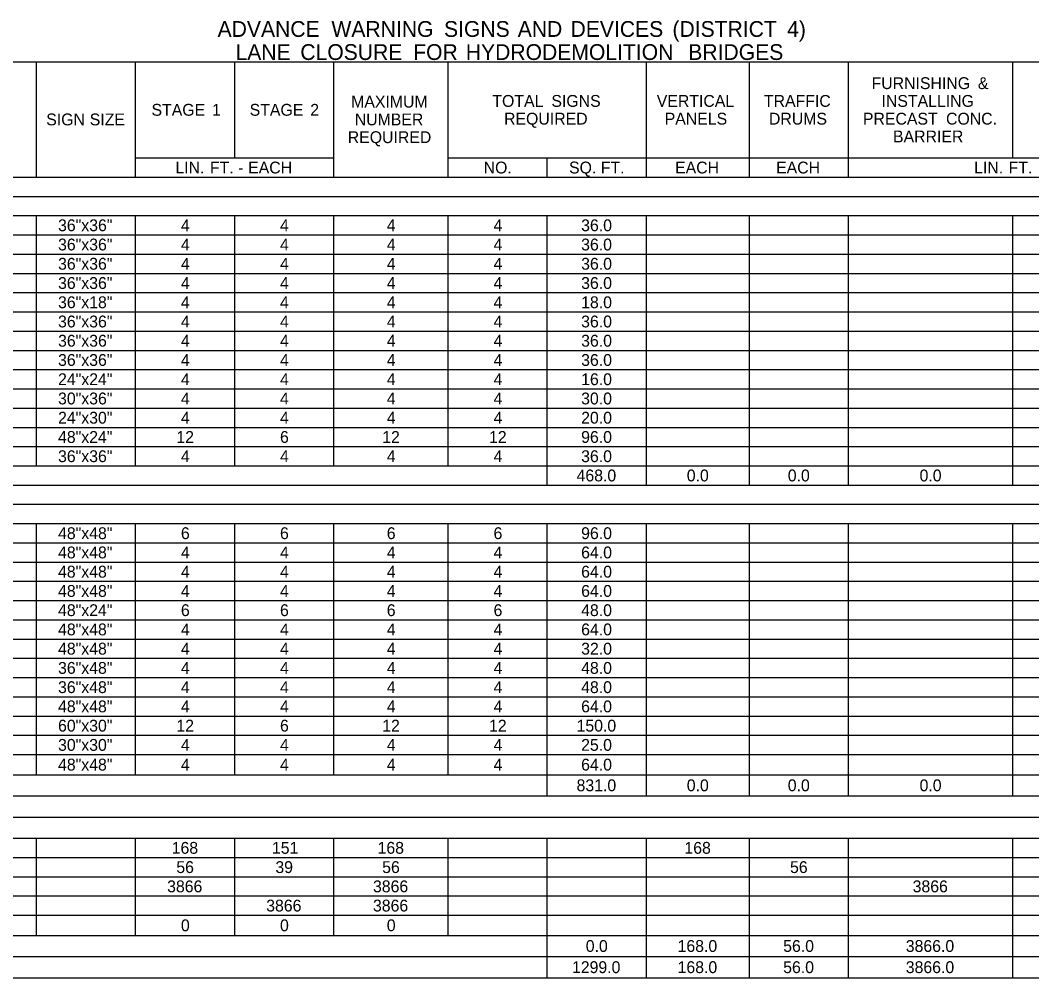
# Model space of a CAD drawing. Extents: x 540541 to 1930787, y -1948574 to 596640.
# Drawn here: x 540863 to 541376, y -1946538 to -1946053 of the extents above; entities that cross this region are included whole.
import ezdxf

# ---------------------------------------------------------------- set-up
doc = ezdxf.new("R2010")
doc.units = 0
doc.layers.add('Default', color=7, linetype='Continuous')

msp = doc.modelspace()

# ---------------------------------------------------------------- linework, layer by layer
at = {"layer": 'Default'}
for p, q in [((540553.71, -1946074), (541684.22, -1946074)), ((540871.56, -1946132.5), (540871.56, -1946074)), ((540921.77, -1946132.5), (540921.77, -1946074)), ((540971.98, -1946122.75), (540971.98, -1946074)), ((541022.2, -1946132.5), (541022.2, -1946074)), ((541080.21, -1946132.5), (541080.21, -1946074)), ((541180.63, -1946132.5), (541180.63, -1946074)), ((541232.8, -1946132.5), (541232.8, -1946074)), ((541283.01, -1946132.5), (541283.01, -1946074)), ((541366.37, -1946122.75), (541366.37, -1946074)), ((540921.77, -1946122.75), (541022.2, -1946122.75)), ((541022.2, -1946132.5), (541022.2, -1946122.75)), ((541080.21, -1946122.75), (541684.22, -1946122.75)), ((541130.42, -1946132.5), (541130.42, -1946122.75)), ((540553.71, -1946132.5), (541684.22, -1946132.5)), ((541022.2, -1946132.5), (541684.22, -1946132.5)), ((540553.71, -1946142.25), (541684.22, -1946142.25)), ((540553.71, -1946152), (541684.22, -1946152)), ((540871.56, -1946278.75), (540871.56, -1946152)), ((540871.56, -1946278.75), (540871.56, -1946152)), ((540921.77, -1946278.75), (540921.77, -1946152)), ((540921.77, -1946278.75), (540921.77, -1946152)), ((540971.98, -1946269), (540971.98, -1946152)), ((540971.98, -1946278.75), (540971.98, -1946152)), ((541022.2, -1946278.75), (541022.2, -1946152)), ((541022.2, -1946278.75), (541022.2, -1946152)), ((541080.21, -1946278.75), (541080.21, -1946152)), ((541130.42, -1946278.75), (541130.42, -1946152)), ((541130.42, -1946288.5), (541130.42, -1946152)), ((541180.63, -1946288.5), (541180.63, -1946152)), ((541180.63, -1946288.5), (541180.63, -1946152)), ((541232.8, -1946288.5), (541232.8, -1946152)), ((541232.8, -1946288.5), (541232.8, -1946152)), ((541283.01, -1946288.5), (541283.01, -1946152)), ((541283.01, -1946288.5), (541283.01, -1946152)), ((541366.37, -1946288.5), (541366.37, -1946152)), ((541366.37, -1946288.5), (541366.37, -1946152)), ((540553.71, -1946161.75), (541684.22, -1946161.75)), ((540553.71, -1946171.5), (541684.22, -1946171.5)), ((540553.71, -1946181.25), (541684.22, -1946181.25)), ((540553.71, -1946191), (541684.22, -1946191)), ((540553.71, -1946200.75), (541684.22, -1946200.75)), ((540553.71, -1946210.5), (541684.22, -1946210.5)), ((540553.71, -1946220.25), (541684.22, -1946220.25)), ((540553.71, -1946230), (541684.22, -1946230)), ((540553.71, -1946239.75), (541684.22, -1946239.75)), ((540553.71, -1946249.5), (541684.22, -1946249.5)), ((540553.71, -1946259.25), (541684.22, -1946259.25)), ((540553.71, -1946269), (541684.22, -1946269)), ((540553.71, -1946278.75), (540921.77, -1946278.75)), ((540553.71, -1946278.75), (540871.56, -1946278.75)), ((540871.56, -1946278.75), (541180.63, -1946278.75)), ((540971.98, -1946278.75), (541022.2, -1946278.75)), ((541022.2, -1946278.75), (541130.42, -1946278.75)), ((541130.42, -1946278.75), (541180.63, -1946278.75)), ((541180.63, -1946278.75), (541684.22, -1946278.75)), ((540553.71, -1946288.5), (541684.22, -1946288.5)), ((540553.71, -1946298.25), (541684.22, -1946298.25)), ((540553.71, -1946308), (541684.22, -1946308)), ((540871.56, -1946435.24), (540871.56, -1946308)), ((540871.56, -1946435.24), (540871.56, -1946308)), ((540921.77, -1946435.24), (540921.77, -1946308)), ((540921.77, -1946435.24), (540921.77, -1946308)), ((540971.98, -1946435.24), (540971.98, -1946308)), ((540971.98, -1946435.24), (540971.98, -1946308)), ((541022.2, -1946435.24), (541022.2, -1946308)), ((541022.2, -1946435.24), (541022.2, -1946308)), ((541080.21, -1946435.24), (541080.21, -1946308)), ((541130.42, -1946445.96), (541130.42, -1946308)), ((541130.42, -1946445.96), (541130.42, -1946308)), ((541180.63, -1946445.96), (541180.63, -1946308)), ((541180.63, -1946445.96), (541180.63, -1946308)), ((541232.8, -1946445.96), (541232.8, -1946308)), ((541232.8, -1946445.96), (541232.8, -1946308)), ((541283.01, -1946445.96), (541283.01, -1946308)), ((541283.01, -1946445.96), (541283.01, -1946308)), ((541366.37, -1946445.96), (541366.37, -1946308)), ((541366.37, -1946445.96), (541366.37, -1946308)), ((540553.71, -1946317.75), (541684.22, -1946317.75)), ((540553.71, -1946327.5), (541684.22, -1946327.5)), ((540553.71, -1946337.25), (541684.22, -1946337.25)), ((540553.71, -1946347), (541684.22, -1946347)), ((540553.71, -1946356.75), (541684.22, -1946356.75)), ((540553.71, -1946366.5), (541684.22, -1946366.5)), ((540553.71, -1946376.25), (541684.22, -1946376.25)), ((540553.71, -1946386), (541684.22, -1946386)), ((540553.71, -1946395.75), (541684.22, -1946395.75)), ((540553.71, -1946405.5), (541684.22, -1946405.5)), ((540553.71, -1946415.25), (541684.22, -1946415.25)), ((540553.71, -1946425), (541684.22, -1946425)), ((540553.71, -1946435.24), (541684.22, -1946435.24)), ((540553.71, -1946435.24), (541684.22, -1946435.24)), ((540553.71, -1946445.96), (541684.22, -1946445.96)), ((540553.71, -1946456.69), (541684.22, -1946456.69)), ((540553.71, -1946467.41), (541684.22, -1946467.41)), ((540871.56, -1946516.65), (540871.56, -1946467.41)), ((540871.56, -1946516.65), (540871.56, -1946467.41)), ((540921.77, -1946516.65), (540921.77, -1946467.41)), ((540921.77, -1946516.65), (540921.77, -1946467.41)), ((540971.98, -1946516.65), (540971.98, -1946467.41)), ((540971.98, -1946516.65), (540971.98, -1946467.41)), ((541022.2, -1946516.65), (541022.2, -1946467.41)), ((541022.2, -1946516.65), (541022.2, -1946467.41)), ((541080.21, -1946516.65), (541080.21, -1946467.41)), ((541130.42, -1946538.1), (541130.42, -1946467.41)), ((541130.42, -1946538.1), (541130.42, -1946467.41)), ((541180.63, -1946538.1), (541180.63, -1946467.41)), ((541180.63, -1946538.1), (541180.63, -1946467.41)), ((541232.8, -1946538.1), (541232.8, -1946467.41)), ((541232.8, -1946538.1), (541232.8, -1946467.41)), ((541283.01, -1946538.1), (541283.01, -1946467.41)), ((541283.01, -1946538.1), (541283.01, -1946467.41)), ((541366.37, -1946538.1), (541366.37, -1946467.41)), ((541366.37, -1946538.1), (541366.37, -1946467.41)), ((540553.71, -1946477.16), (541684.22, -1946477.16)), ((540553.71, -1946486.91), (541684.22, -1946486.91)), ((540553.71, -1946496.66), (541022.2, -1946496.66)), ((540871.56, -1946496.66), (541022.2, -1946496.66)), ((541022.2, -1946496.66), (541366.37, -1946496.66)), ((541080.21, -1946496.66), (541283.01, -1946496.66)), ((541283.01, -1946496.66), (541684.22, -1946496.66)), ((540553.71, -1946506.41), (541684.22, -1946506.41)), ((540553.71, -1946516.65), (541684.22, -1946516.65)), ((540553.71, -1946516.65), (541684.22, -1946516.65)), ((540553.71, -1946527.38), (541684.22, -1946527.38)), ((540553.71, -1946538.1), (541684.22, -1946538.1))]:
    msp.add_line(p, q, dxfattribs=at)

# ---------------------------------------------------------------- texts
for s, height, p in [('ADVANCE', 8, (540963.32, -1946061.43)), (' WARNING', 8, (541018.04, -1946061.43)), (' SIGNS', 8, (541075.11, -1946061.43)), (' DEVICES', 8, (541139.22, -1946061.43)), (' (DISTRICT', 8, (541190.86, -1946061.43)), (' 4)', 8, (541248.99, -1946061.43)), (' AND', 8, (541112.45, -1946061.43)), ('LANE', 8, (540972.4, -1946073.13)), (' CLOSURE', 8, (541002.28, -1946073.13)), (' FOR', 8, (541059.48, -1946073.13)), (' HYDRODEMOLITION', 8, (541086.13, -1946073.13)), (' BRIDGES', 8, (541198.88, -1946073.13)), ('FURNISHING', 6, (541294.74, -1946087.88)), (' &', 6, (541346.4, -1946087.88)), ('MAXIMUM', 6, (541031.01, -1946097.25)), ('TOTAL', 6, (541102.57, -1946096.88)), (' SIGNS', 6, (541130.26, -1946096.88)), ('VERTICAL', 6, (541185.88, -1946096.88)), ('TRAFFIC', 6, (541240.19, -1946096.88)), ('INSTALLING', 6, (541299.79, -1946096.88)), ('STAGE', 6, (540929.83, -1946101.38)), (' 1', 6, (540958.3, -1946101.38)), ('STAGE', 6, (540979.57, -1946101.38)), (' 2', 6, (541008.04, -1946101.38)), ('SIGN', 6, (540876.48, -1946106.25)), (' SIZE', 6, (540896.3, -1946106.25)), ('NUMBER', 6, (541032.82, -1946106.25)), ('REQUIRED', 6, (541108.5, -1946105.88)), ('PANELS', 6, (541189.91, -1946105.88)), ('DRUMS', 6, (541242.74, -1946105.88)), ('PRECAST', 6, (541290.36, -1946105.88)), (' CONC.', 6, (541330.25, -1946105.88)), ('REQUIRED', 6, (541029.28, -1946115.25)), ('BARRIER', 6, (541305.61, -1946114.88)), ('LIN.', 6, (540941.94, -1946130.63)), (' FT.', 6, (540957.2, -1946130.63)), (' EACH', 6, (540976.58, -1946130.63)), ('NO.', 6, (541098.15, -1946130.63)), ('SQ.', 6, (541141.43, -1946130.63)), (' FT.', 6, (541155.3, -1946130.63)), ('EACH', 6, (541195.16, -1946130.63)), ('EACH', 6, (541246.35, -1946130.63)), ('LIN.', 6, (541346.71, -1946130.63)), (' FT.', 6, (541361.96, -1946130.63)), (' -', 6, (540971.52, -1946130.63)), ('36"x36"', 6, (540882.47, -1946159.88)), ('4', 6, (540944.75, -1946159.88)), ('4', 6, (540994.96, -1946159.88)), ('4', 6, (541049.08, -1946159.88)), ('4', 6, (541103.19, -1946159.88)), ('36.0', 6, (541147.57, -1946159.88)), ('36"x36"', 6, (540882.47, -1946169.63)), ('4', 6, (540944.75, -1946169.63)), ('4', 6, (540994.96, -1946169.63)), ('4', 6, (541049.08, -1946169.63)), ('4', 6, (541103.19, -1946169.63)), ('36.0', 6, (541147.57, -1946169.63)), ('36"x36"', 6, (540882.47, -1946179.38)), ('4', 6, (540944.75, -1946179.38)), ('4', 6, (540994.96, -1946179.38)), ('4', 6, (541049.08, -1946179.38)), ('4', 6, (541103.19, -1946179.38)), ('36.0', 6, (541147.57, -1946179.38)), ('36"x36"', 6, (540882.47, -1946189.13)), ('4', 6, (540944.75, -1946189.13)), ('4', 6, (540994.96, -1946189.13)), ('4', 6, (541049.08, -1946189.13)), ('4', 6, (541103.19, -1946189.13)), ('36.0', 6, (541147.57, -1946189.13)), ('36"x18"', 6, (540882.47, -1946198.88)), ('4', 6, (540944.75, -1946198.88)), ('4', 6, (540994.96, -1946198.88)), ('4', 6, (541049.08, -1946198.88)), ('4', 6, (541103.19, -1946198.88)), ('18.0', 6, (541147.57, -1946198.88)), ('36"x36"', 6, (540882.47, -1946208.63)), ('4', 6, (540944.75, -1946208.63)), ('4', 6, (540994.96, -1946208.63)), ('4', 6, (541049.08, -1946208.63)), ('4', 6, (541103.19, -1946208.63)), ('36.0', 6, (541147.57, -1946208.63)), ('36"x36"', 6, (540882.47, -1946218.38)), ('4', 6, (540944.75, -1946218.38)), ('4', 6, (540994.96, -1946218.38)), ('4', 6, (541049.08, -1946218.38)), ('4', 6, (541103.19, -1946218.38)), ('36.0', 6, (541147.57, -1946218.38)), ('36"x36"', 6, (540882.47, -1946228.13)), ('4', 6, (540944.75, -1946228.13)), ('4', 6, (540994.96, -1946228.13)), ('4', 6, (541049.08, -1946228.13)), ('4', 6, (541103.19, -1946228.13)), ('36.0', 6, (541147.57, -1946228.13)), ('24"x24"', 6, (540882.47, -1946237.88)), ('4', 6, (540944.75, -1946237.88)), ('4', 6, (540994.96, -1946237.88)), ('4', 6, (541049.08, -1946237.88)), ('4', 6, (541103.19, -1946237.88)), ('16.0', 6, (541147.57, -1946237.88)), ('30"x36"', 6, (540882.47, -1946247.63)), ('4', 6, (540944.75, -1946247.63)), ('4', 6, (540994.96, -1946247.63)), ('4', 6, (541049.08, -1946247.63)), ('4', 6, (541103.19, -1946247.63)), ('30.0', 6, (541147.57, -1946247.63)), ('24"x30"', 6, (540882.47, -1946257.38)), ('4', 6, (540944.75, -1946257.38)), ('4', 6, (540994.96, -1946257.38)), ('4', 6, (541049.08, -1946257.38)), ('4', 6, (541103.19, -1946257.38)), ('20.0', 6, (541147.57, -1946257.38)), ('48"x24"', 6, (540882.47, -1946267.13)), ('12', 6, (540942.44, -1946267.13)), ('6', 6, (540994.95, -1946267.13)), ('12', 6, (541046.76, -1946267.13)), ('12', 6, (541100.88, -1946267.13)), ('96.0', 6, (541147.57, -1946267.13)), ('36"x36"', 6, (540882.47, -1946276.88)), ('4', 6, (540944.75, -1946276.88)), ('4', 6, (540994.96, -1946276.88)), ('4', 6, (541049.08, -1946276.88)), ('4', 6, (541103.19, -1946276.88)), ('36.0', 6, (541147.57, -1946276.88)), ('468.0', 6, (541145.25, -1946286.63)), ('0.0', 6, (541201.1, -1946286.63)), ('0.0', 6, (541252.28, -1946286.63)), ('0.0', 6, (541319.07, -1946286.63)), ('48"x48"', 6, (540882.47, -1946315.88)), ('6', 6, (540944.74, -1946315.88)), ('6', 6, (540994.95, -1946315.88)), ('6', 6, (541049.06, -1946315.88)), ('6', 6, (541103.17, -1946315.88)), ('96.0', 6, (541147.57, -1946315.88)), ('48"x48"', 6, (540882.47, -1946325.63)), ('4', 6, (540944.75, -1946325.63)), ('4', 6, (540994.96, -1946325.63)), ('4', 6, (541049.08, -1946325.63)), ('4', 6, (541103.19, -1946325.63)), ('64.0', 6, (541147.57, -1946325.63)), ('48"x48"', 6, (540882.47, -1946335.38)), ('4', 6, (540944.75, -1946335.38)), ('4', 6, (540994.96, -1946335.38)), ('4', 6, (541049.08, -1946335.38)), ('4', 6, (541103.19, -1946335.38)), ('64.0', 6, (541147.57, -1946335.38)), ('48"x48"', 6, (540882.47, -1946345.13)), ('4', 6, (540944.75, -1946345.13)), ('4', 6, (540994.96, -1946345.13)), ('4', 6, (541049.08, -1946345.13)), ('4', 6, (541103.19, -1946345.13)), ('64.0', 6, (541147.57, -1946345.13)), ('48"x24"', 6, (540882.47, -1946354.88)), ('6', 6, (540944.74, -1946354.88)), ('6', 6, (540994.95, -1946354.88)), ('6', 6, (541049.06, -1946354.88)), ('6', 6, (541103.17, -1946354.88)), ('48.0', 6, (541147.57, -1946354.88)), ('48"x48"', 6, (540882.47, -1946364.63)), ('4', 6, (540944.75, -1946364.63)), ('4', 6, (540994.96, -1946364.63)), ('4', 6, (541049.08, -1946364.63)), ('4', 6, (541103.19, -1946364.63)), ('64.0', 6, (541147.57, -1946364.63)), ('48"x48"', 6, (540882.47, -1946374.38)), ('4', 6, (540944.75, -1946374.38)), ('4', 6, (540994.96, -1946374.38)), ('4', 6, (541049.08, -1946374.38)), ('4', 6, (541103.19, -1946374.38)), ('32.0', 6, (541147.57, -1946374.38)), ('36"x48"', 6, (540882.47, -1946384.13)), ('4', 6, (540944.75, -1946384.13)), ('4', 6, (540994.96, -1946384.13)), ('4', 6, (541049.08, -1946384.13)), ('4', 6, (541103.19, -1946384.13)), ('48.0', 6, (541147.57, -1946384.13)), ('36"x48"', 6, (540882.47, -1946393.88)), ('4', 6, (540944.75, -1946393.88)), ('4', 6, (540994.96, -1946393.88)), ('4', 6, (541049.08, -1946393.88)), ('4', 6, (541103.19, -1946393.88)), ('48.0', 6, (541147.57, -1946393.88)), ('48"x48"', 6, (540882.47, -1946403.63)), ('4', 6, (540944.75, -1946403.63)), ('4', 6, (540994.96, -1946403.63)), ('4', 6, (541049.08, -1946403.63)), ('4', 6, (541103.19, -1946403.63)), ('64.0', 6, (541147.57, -1946403.63)), ('60"x30"', 6, (540882.47, -1946413.38)), ('12', 6, (540942.44, -1946413.38)), ('6', 6, (540994.95, -1946413.38)), ('12', 6, (541046.76, -1946413.38)), ('12', 6, (541100.88, -1946413.38)), ('150.0', 6, (541145.24, -1946413.38)), ('30"x30"', 6, (540882.47, -1946423.13)), ('4', 6, (540944.75, -1946423.13)), ('4', 6, (540994.96, -1946423.13)), ('4', 6, (541049.08, -1946423.13)), ('4', 6, (541103.19, -1946423.13)), ('25.0', 6, (541147.57, -1946423.13)), ('48"x48"', 6, (540882.47, -1946433.12)), ('4', 6, (540944.75, -1946433.12)), ('4', 6, (540994.96, -1946433.12)), ('4', 6, (541049.08, -1946433.12)), ('4', 6, (541103.19, -1946433.12)), ('64.0', 6, (541147.57, -1946433.12)), ('831.0', 6, (541145.25, -1946443.6)), ('0.0', 6, (541201.1, -1946443.6)), ('0.0', 6, (541252.28, -1946443.6)), ('0.0', 6, (541319.07, -1946443.6)), ('168', 6, (540940.07, -1946475.29)), ('151', 6, (540990.87, -1946475.29)), ('168', 6, (541044.4, -1946475.29)), ('168', 6, (541199.91, -1946475.29)), ('56', 6, (540942.41, -1946485.04)), ('39', 6, (540992.61, -1946485.04)), ('56', 6, (541046.73, -1946485.04)), ('56', 6, (541253.43, -1946485.04)), ('3866', 6, (540937.75, -1946494.79)), ('3866', 6, (541042.07, -1946494.79)), ('3866', 6, (541315.56, -1946494.79)), ('3866', 6, (540987.96, -1946504.54)), ('3866', 6, (541042.07, -1946504.54)), ('0', 6, (540944.75, -1946514.53)), ('0', 6, (540994.96, -1946514.53)), ('0', 6, (541049.07, -1946514.53)), ('0.0', 6, (541149.91, -1946525.01)), ('168.0', 6, (541196.44, -1946525.01)), ('56.0', 6, (541249.95, -1946525.01)), ('3866.0', 6, (541312.08, -1946525.01)), ('1299.0', 6, (541142.92, -1946535.74)), ('168.0', 6, (541196.44, -1946535.74)), ('56.0', 6, (541249.95, -1946535.74)), ('3866.0', 6, (541312.08, -1946535.74))]:
    msp.add_text(s, height=height, dxfattribs=at).set_placement(p)

doc.saveas('drawing.dxf')
